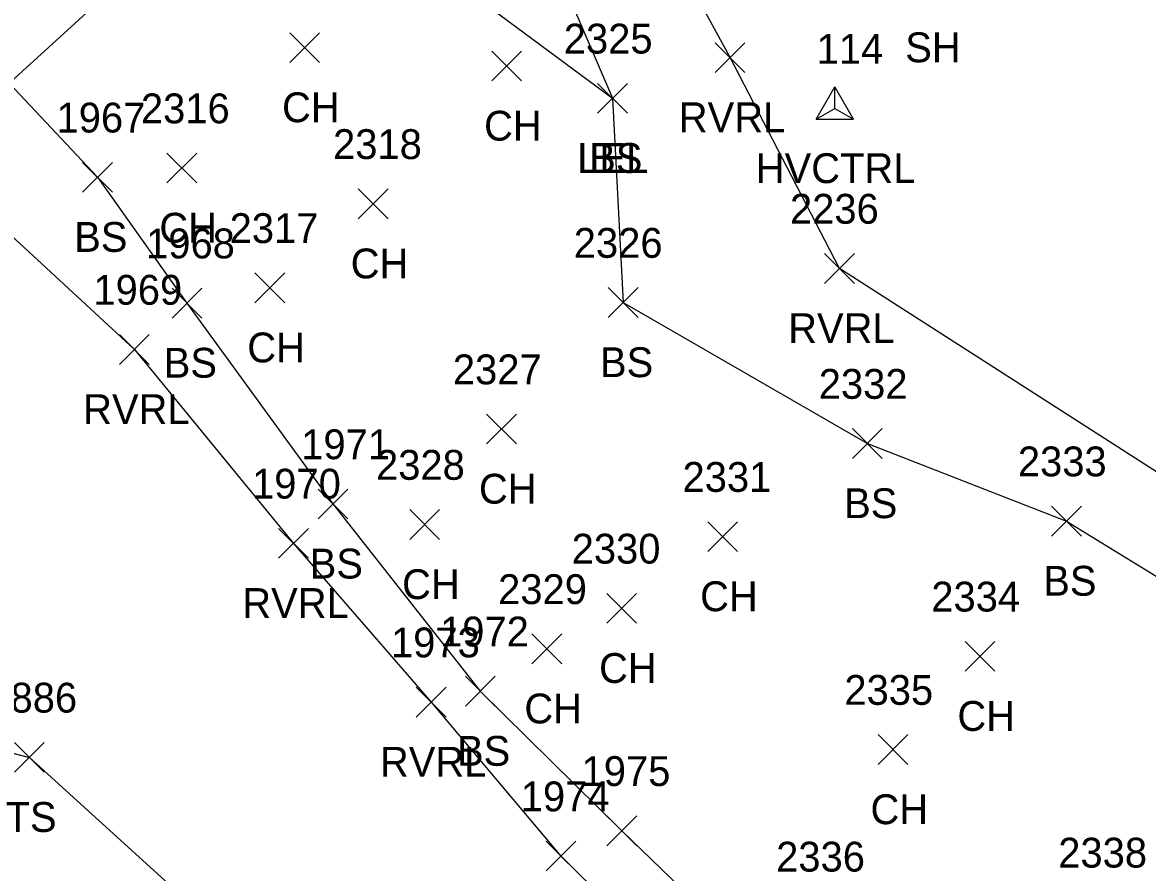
# Model space of a CAD drawing. Extents: x 1647133 to 1649138, y 411736 to 414924.
# Drawn here: x 1648877.6 to 1648953, y 412063.3 to 412120.2 of the extents above; entities that cross this region are included whole.
import ezdxf

# ---------------------------------------------------------------- set-up
doc = ezdxf.new("R2010")
doc.units = 0
for name, color, linetype in [('BELB', 7, 'Continuous'), ('C_A', 7, 'Continuous'), ('C_I', 7, 'Continuous'), ('CPSM', 7, 'Continuous'), ('L_A', 7, 'Continuous'), ('L_I', 7, 'Continuous'), ('L_TIC', 7, 'Continuous'), ('LARO', 7, 'Continuous'), ('LAWE', 7, 'Continuous'), ('LELB', 7, 'Continuous')]:
    doc.layers.add(name, color=color, linetype=linetype)

msp = doc.modelspace()

# ---------------------------------------------------------------- linework, layer by layer
at = {"layer": 'BELB'}
msp.add_lwpolyline([(1648856.366, 412097.638), (1648904.081, 412141.155), (1648932.964, 412166.557), (1648970.055, 412199.522), (1648985.33, 412212.818), (1648974.892, 412224.907)], dxfattribs=at)
at = {"layer": 'CPSM'}
for p, q in [((1648930.772, 412113.747), (1648932.022, 412115.912)), ((1648933.272, 412113.747), (1648932.022, 412115.912)), ((1648932.022, 412114.469), (1648932.022, 412115.912)), ((1648930.772, 412113.747), (1648932.022, 412114.469)), ((1648932.022, 412114.469), (1648932.022, 412114.469)), ((1648932.022, 412114.469), (1648933.272, 412113.747)), ((1648930.772, 412113.747), (1648933.272, 412113.747))]:
    msp.add_line(p, q, dxfattribs=at)
at = {"layer": 'L_TIC'}
for points in [[(1648895.485, 412117.552), (1648897.485, 412119.552)], [(1648897.485, 412117.552), (1648895.485, 412119.552)], [(1648909.02, 412116.316), (1648911.02, 412118.316)], [(1648911.02, 412116.316), (1648909.02, 412118.316)], [(1648923.989, 412116.882), (1648925.989, 412118.882)], [(1648925.989, 412116.882), (1648923.989, 412118.882)], [(1648916.111, 412114.154), (1648918.111, 412116.154)], [(1648918.111, 412114.154), (1648916.111, 412116.154)], [(1648916.111, 412114.154), (1648918.111, 412116.154)], [(1648918.111, 412114.154), (1648916.111, 412116.154)], [(1648887.264, 412109.477), (1648889.264, 412111.477)], [(1648889.264, 412109.477), (1648887.264, 412111.477)], [(1648881.604, 412108.86), (1648883.604, 412110.86)], [(1648883.604, 412108.86), (1648881.604, 412110.86)], [(1648900.084, 412107.082), (1648902.084, 412109.082)], [(1648902.084, 412107.082), (1648900.084, 412109.082)], [(1648931.321, 412102.746), (1648933.321, 412104.746)], [(1648933.321, 412102.746), (1648931.321, 412104.746)], [(1648893.155, 412101.449), (1648895.155, 412103.449)], [(1648895.155, 412101.449), (1648893.155, 412103.449)], [(1648887.604, 412100.424), (1648889.604, 412102.424)], [(1648889.604, 412100.424), (1648887.604, 412102.424)], [(1648916.834, 412100.461), (1648918.834, 412102.461)], [(1648918.834, 412100.461), (1648916.834, 412102.461)], [(1648884.08, 412097.314), (1648886.08, 412099.314)], [(1648886.08, 412097.314), (1648884.08, 412099.314)], [(1648908.678, 412091.98), (1648910.678, 412093.98)], [(1648910.678, 412091.98), (1648908.678, 412093.98)], [(1648933.194, 412091.008), (1648935.194, 412093.008)], [(1648935.194, 412091.008), (1648933.194, 412093.008)], [(1648897.385, 412086.961), (1648899.385, 412088.961)], [(1648899.385, 412086.961), (1648897.385, 412088.961)], [(1648903.53, 412085.58), (1648905.53, 412087.58)], [(1648905.53, 412085.58), (1648903.53, 412087.58)], [(1648946.536, 412085.809), (1648948.536, 412087.809)], [(1648948.536, 412085.809), (1648946.536, 412087.809)], [(1648923.498, 412084.77), (1648925.498, 412086.77)], [(1648925.498, 412084.77), (1648923.498, 412086.77)], [(1648894.742, 412084.318), (1648896.742, 412086.318)], [(1648896.742, 412084.318), (1648894.742, 412086.318)], [(1648916.726, 412079.962), (1648918.726, 412081.962)], [(1648918.726, 412079.962), (1648916.726, 412081.962)], [(1648911.719, 412077.247), (1648913.719, 412079.247)], [(1648913.719, 412077.247), (1648911.719, 412079.247)], [(1648940.736, 412076.748), (1648942.736, 412078.748)], [(1648942.736, 412076.748), (1648940.736, 412078.748)], [(1648907.255, 412074.407), (1648909.255, 412076.407)], [(1648909.255, 412074.407), (1648907.255, 412076.407)], [(1648903.966, 412073.676), (1648905.966, 412075.676)], [(1648905.966, 412073.676), (1648903.966, 412075.676)], [(1648934.912, 412070.493), (1648936.912, 412072.493)], [(1648936.912, 412070.493), (1648934.912, 412072.493)], [(1648877.04, 412069.973), (1648879.04, 412071.973)], [(1648879.04, 412069.973), (1648877.04, 412071.973)], [(1648916.737, 412065.051), (1648918.737, 412067.051)], [(1648918.737, 412065.051), (1648916.737, 412067.051)], [(1648912.662, 412063.354), (1648914.662, 412065.354)], [(1648914.662, 412063.354), (1648912.662, 412065.354)]]:
    msp.add_lwpolyline(points, dxfattribs=at)
at = {"layer": 'LARO'}
msp.add_lwpolyline([(1648905.854, 412138.123), (1648904.419, 412134.508), (1648903.138, 412125.533), (1648917.111, 412115.154)], dxfattribs=at)
at = {"layer": 'LAWE'}
for points in [[(1648975.479, 412083.808), (1648956.323, 412088.342), (1648932.321, 412103.746), (1648924.989, 412117.882), (1648915.837, 412134.668), (1648909.22, 412137.093)], [(1648837.128, 412133.097), (1648849.111, 412130.576), (1648858.551, 412123.429), (1648865.22, 412116.653), (1648885.08, 412098.314), (1648895.742, 412085.318), (1648904.966, 412074.676), (1648913.662, 412064.354), (1648932.191, 412046.181), (1648949.069, 412033.32)]]:
    msp.add_lwpolyline(points, dxfattribs=at)
at = {"layer": 'LELB'}
for points in [[(1648905.543, 412134.547), (1648909.562, 412132.742), (1648917.111, 412115.154), (1648917.834, 412101.461), (1648934.194, 412092.008), (1648947.536, 412086.809), (1648962.617, 412077.56), (1648983.8, 412066.358)], [(1648875.311, 412117.612), (1648882.604, 412109.86), (1648888.604, 412101.424), (1648898.385, 412087.961), (1648908.255, 412075.407), (1648917.737, 412066.051), (1648935.47, 412048.917), (1648951.031, 412035.933)], [(1648870.706, 412072.868), (1648878.04, 412070.973), (1648905.433, 412046.074), (1648939.422, 412014.67)]]:
    msp.add_lwpolyline(points, dxfattribs=at)

# ---------------------------------------------------------------- texts
at = {"layer": 'C_A'}
msp.add_text('HVCTRL', height=2, dxfattribs=at).set_placement((1648926.715, 412109.469))
at = {"layer": 'C_I'}
msp.add_text('114', height=2, dxfattribs=at).set_placement((1648930.794, 412117.469))
at = {"layer": 'L_A'}
for s, p in [('SH', (1648936.731, 412117.57)), ('CH', (1648894.973, 412113.552)), ('RVRL', (1648921.556, 412112.882)), ('CH', (1648908.508, 412112.316)), ('BS', (1648915.552, 412110.154)), ('LEL', (1648914.749, 412110.154)), ('CH', (1648886.752, 412105.477)), ('BS', (1648881.045, 412104.86)), ('CH', (1648899.572, 412103.082)), ('RVRL', (1648928.888, 412098.746)), ('CH', (1648892.643, 412097.449)), ('BS', (1648887.045, 412096.424)), ('BS', (1648916.275, 412096.461)), ('RVRL', (1648881.647, 412093.314)), ('CH', (1648908.166, 412087.98)), ('BS', (1648932.635, 412087.008)), ('BS', (1648896.826, 412082.961)), ('CH', (1648903.018, 412081.58)), ('BS', (1648945.977, 412081.809)), ('CH', (1648922.986, 412080.77)), ('RVRL', (1648892.309, 412080.318)), ('CH', (1648916.214, 412075.962)), ('CH', (1648911.207, 412073.247)), ('CH', (1648940.224, 412072.748)), ('BS', (1648906.695, 412070.407)), ('RVRL', (1648901.533, 412069.676)), ('CH', (1648934.4, 412066.493)), ('TS', (1648876.45, 412065.973))]:
    msp.add_text(s, height=2, dxfattribs=at).set_placement(p)
at = {"layer": 'L_I'}
for s, p in [('2325', (1648913.851, 412118.154)), ('2325', (1648913.851, 412118.154)), ('2316', (1648885.516, 412113.477)), ('1967', (1648879.864, 412112.86)), ('2318', (1648898.391, 412111.082)), ('2236', (1648929.006, 412106.746)), ('2317', (1648891.462, 412105.449)), ('1968', (1648885.864, 412104.424)), ('2326', (1648914.519, 412104.461)), ('1969', (1648882.332, 412101.314)), ('2327', (1648906.418, 412095.98)), ('2332', (1648930.934, 412095.008)), ('1971', (1648896.259, 412090.961)), ('2333', (1648944.276, 412089.809)), ('2328', (1648901.27, 412089.58)), ('1970', (1648892.963, 412088.318)), ('2331', (1648921.805, 412088.77)), ('2330', (1648914.379, 412083.962)), ('2329', (1648909.451, 412081.247)), ('2334', (1648938.476, 412080.748)), ('1972', (1648905.562, 412078.407)), ('1973', (1648902.273, 412077.676)), ('1886', (1648875.292, 412073.973)), ('2335', (1648932.652, 412074.493)), ('1975', (1648915.044, 412069.051)), ('1974', (1648910.969, 412067.354)), ('2338', (1648946.981, 412063.583)), ('2336', (1648928.08, 412063.315))]:
    msp.add_text(s, height=2, dxfattribs=at).set_placement(p)

doc.saveas('drawing.dxf')
